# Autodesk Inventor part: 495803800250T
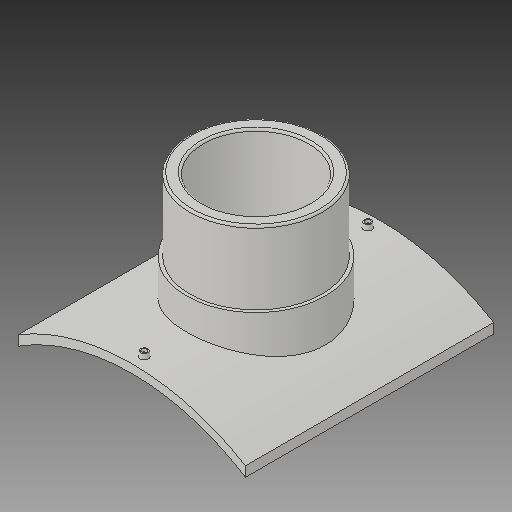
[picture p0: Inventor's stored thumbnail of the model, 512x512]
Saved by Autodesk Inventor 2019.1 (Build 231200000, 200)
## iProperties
Created: 2017-10
Part Number: 495803800250T
Material: Generic
Description: PLASSON BRANCH SADDLE  800x250
Document SubType Name: Modeling
Designer: KIM
Mass: 2754.05 g
Surface Area: 3037.44 cm^2
Volume: 2754.05 cm^3
Density: 1 g/cm^3
Appearance: Default
Author: KIM
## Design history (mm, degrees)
derived "495803.ipt"
feature "Solid1::495803.ipt"
tag "TaggingFeature1"
body "Solid1"
other parameters: "d1" = 16, "d4" = 0, "d12" = 425.6, "d13" = 14, "d14" = 211.5, "d16" = 5 deg, "d18" = 4, "d19" = 14, "d20" = 0, "d21" = 3, "d22" = 0, "d23" = 613, "d24" = 262.5, "d25" = 16, "d28" = 0, "d29" = 9.6, "d31" = 0, "d32" = 98.5, "d33" = 0, "d34" = 8, "d37" = 137.9, "d38" = 0, "d39" = 4, "H_" = 197, "x_" = 16, "D_" = 16
